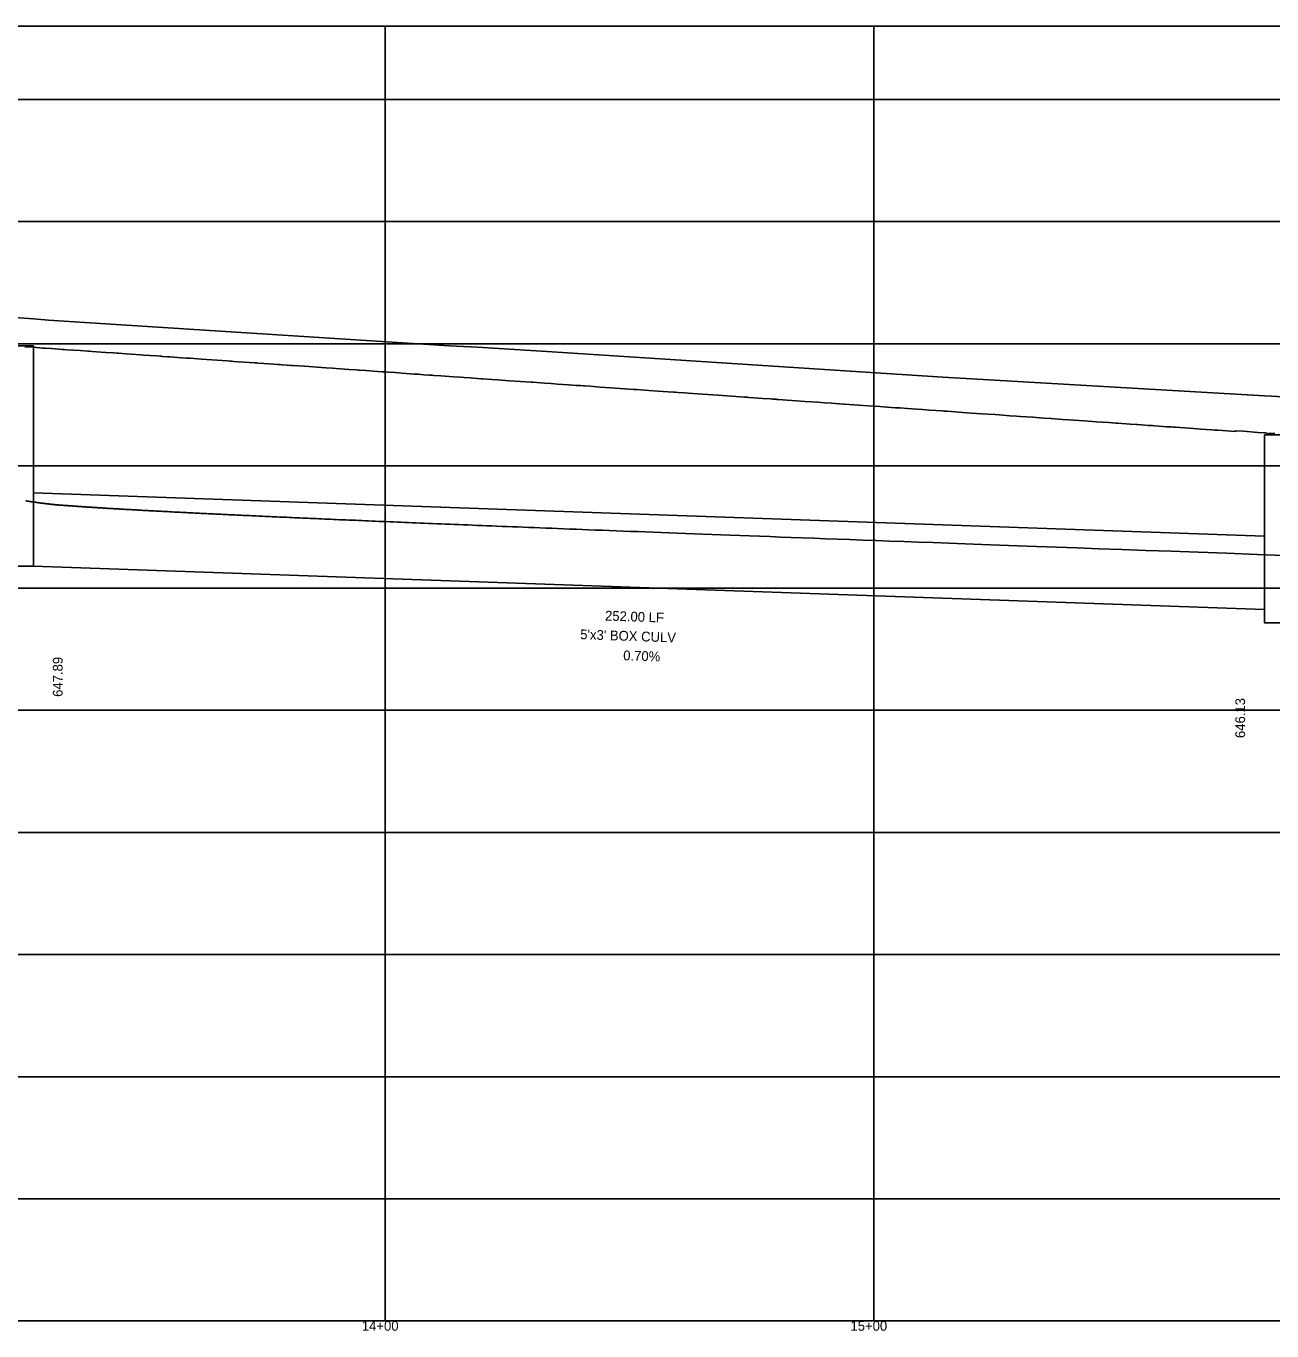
# Model space of a CAD drawing. Extents: x 2252703 to 2264864, y 13787568 to 13790989.
# Drawn here: x 2259238.5 to 2259493.5, y 13790698.5 to 13790965.5 of the extents above; entities that cross this region are included whole.
import ezdxf

# ---------------------------------------------------------------- set-up
doc = ezdxf.new("R2010")
doc.units = 0
for name, color, linetype in [('blank4', 7, 'Continuous'), ('D_DRN_PROF_HGL', 7, 'Continuous'), ('D_PROF_1', 7, 'Continuous'), ('D_PROF_NOTES_1', 7, 'Continuous'), ('Default', 7, 'Continuous'), ('Drain_PipeInside', 7, 'Continuous'), ('E_Terrain', 7, 'Continuous'), ('Inlet', 7, 'Continuous'), ('z - Construction', 7, 'Continuous')]:
    doc.layers.add(name, color=color, linetype=linetype)

msp = doc.modelspace()

# ---------------------------------------------------------------- linework, layer by layer
at = {"layer": 'blank4'}
msp.add_lwpolyline([(2257912.03, 13790700.51), (2257912.03, 13790965.51), (2261066.03, 13790965.51), (2261066.03, 13790700.51)], close=True, dxfattribs=at)
at = {"layer": 'D_DRN_PROF_HGL'}
msp.add_lwpolyline([(2259238.49, 13790868.35), (2259238.54, 13790868.34), (2259238.59, 13790868.34), (2259238.64, 13790868.33), (2259238.7, 13790868.32), (2259238.75, 13790868.31), (2259238.8, 13790868.3), (2259238.86, 13790868.29), (2259238.91, 13790868.28), (2259238.97, 13790868.27), (2259239.02, 13790868.27), (2259239.08, 13790868.26), (2259239.14, 13790868.25), (2259239.2, 13790868.24), (2259239.26, 13790868.23), (2259239.32, 13790868.22), (2259239.38, 13790868.21), (2259239.44, 13790868.2), (2259239.5, 13790868.19), (2259239.56, 13790868.18), (2259239.62, 13790868.17), (2259239.69, 13790868.16), (2259239.75, 13790868.15), (2259239.82, 13790868.14), (2259239.88, 13790868.14), (2259239.95, 13790868.13), (2259240.02, 13790868.12), (2259240.08, 13790868.11), (2259240.15, 13790868.1), (2259240.22, 13790868.09), (2259240.29, 13790868.08), (2259240.36, 13790868.07), (2259240.43, 13790868.06), (2259240.5, 13790868.05), (2259240.58, 13790868.04), (2259240.65, 13790868.03), (2259240.72, 13790868.02), (2259240.8, 13790868.01), (2259240.87, 13790868), (2259240.95, 13790867.99), (2259241.03, 13790867.98), (2259241.1, 13790867.96), (2259241.18, 13790867.95), (2259241.26, 13790867.94), (2259241.34, 13790867.93), (2259241.42, 13790867.92), (2259241.5, 13790867.91), (2259241.59, 13790867.9), (2259241.67, 13790867.89), (2259241.75, 13790867.88), (2259241.84, 13790867.87), (2259241.92, 13790867.86), (2259242.01, 13790867.85), (2259242.1, 13790867.84), (2259242.19, 13790867.82), (2259242.27, 13790867.81), (2259242.36, 13790867.8), (2259242.45, 13790867.79), (2259242.54, 13790867.78), (2259242.64, 13790867.77), (2259242.73, 13790867.76), (2259242.82, 13790867.74), (2259242.92, 13790867.73), (2259243.01, 13790867.72), (2259243.11, 13790867.71), (2259243.21, 13790867.7), (2259243.3, 13790867.69), (2259243.4, 13790867.67), (2259243.5, 13790867.66), (2259243.6, 13790867.65), (2259243.7, 13790867.64), (2259243.81, 13790867.63), (2259243.91, 13790867.61), (2259244.01, 13790867.6), (2259244.12, 13790867.59), (2259244.22, 13790867.58), (2259244.33, 13790867.58), (2259244.44, 13790867.57), (2259244.55, 13790867.56), (2259244.66, 13790867.55), (2259244.77, 13790867.54), (2259244.88, 13790867.53), (2259244.99, 13790867.52), (2259245.1, 13790867.51), (2259245.22, 13790867.5), (2259245.33, 13790867.5), (2259245.45, 13790867.49), (2259245.57, 13790867.48), (2259245.69, 13790867.47), (2259245.8, 13790867.46), (2259245.92, 13790867.45), (2259246.05, 13790867.44), (2259246.17, 13790867.43), (2259246.29, 13790867.42), (2259246.42, 13790867.41), (2259246.54, 13790867.4), (2259246.67, 13790867.39), (2259246.79, 13790867.38), (2259246.92, 13790867.37), (2259247.05, 13790867.37), (2259247.18, 13790867.36), (2259247.32, 13790867.35), (2259247.45, 13790867.34), (2259247.58, 13790867.33), (2259247.72, 13790867.32), (2259247.85, 13790867.31), (2259247.99, 13790867.3), (2259248.13, 13790867.29), (2259248.27, 13790867.28), (2259248.41, 13790867.27), (2259248.55, 13790867.26), (2259248.69, 13790867.25), (2259248.84, 13790867.24), (2259248.98, 13790867.23), (2259249.13, 13790867.22), (2259249.28, 13790867.21), (2259249.43, 13790867.2), (2259249.58, 13790867.19), (2259249.73, 13790867.18), (2259249.88, 13790867.17), (2259250.03, 13790867.16), (2259250.19, 13790867.15), (2259250.34, 13790867.13), (2259250.5, 13790867.12), (2259250.66, 13790867.11), (2259250.82, 13790867.1), (2259250.98, 13790867.09), (2259251.14, 13790867.08), (2259251.31, 13790867.07), (2259251.47, 13790867.06), (2259251.64, 13790867.05), (2259251.81, 13790867.04), (2259251.98, 13790867.03), (2259252.15, 13790867.02), (2259252.32, 13790867.01), (2259252.49, 13790866.99), (2259252.67, 13790866.98), (2259252.84, 13790866.97), (2259253.02, 13790866.96), (2259253.2, 13790866.95), (2259253.38, 13790866.94), (2259253.56, 13790866.93), (2259253.74, 13790866.92), (2259253.93, 13790866.9), (2259254.11, 13790866.89), (2259254.3, 13790866.88), (2259254.49, 13790866.87), (2259254.68, 13790866.86), (2259254.87, 13790866.85), (2259255.07, 13790866.83), (2259255.26, 13790866.82), (2259255.46, 13790866.81), (2259255.66, 13790866.8), (2259255.86, 13790866.79), (2259256.06, 13790866.77), (2259256.26, 13790866.76), (2259256.47, 13790866.75), (2259256.67, 13790866.74), (2259256.88, 13790866.73), (2259257.09, 13790866.71), (2259257.3, 13790866.7), (2259257.51, 13790866.69), (2259257.73, 13790866.68), (2259257.94, 13790866.66), (2259258.16, 13790866.65), (2259258.38, 13790866.64), (2259258.6, 13790866.63), (2259258.83, 13790866.61), (2259259.05, 13790866.6), (2259259.28, 13790866.59), (2259259.51, 13790866.57), (2259259.74, 13790866.56), (2259259.97, 13790866.55), (2259260.21, 13790866.53), (2259260.44, 13790866.52), (2259260.68, 13790866.51), (2259260.92, 13790866.49), (2259261.16, 13790866.48), (2259261.41, 13790866.47), (2259261.65, 13790866.45), (2259261.9, 13790866.44), (2259262.15, 13790866.43), (2259262.4, 13790866.41), (2259262.66, 13790866.4), (2259262.91, 13790866.39), (2259263.17, 13790866.37), (2259263.43, 13790866.36), (2259263.69, 13790866.34), (2259263.96, 13790866.33), (2259264.22, 13790866.31), (2259264.49, 13790866.3), (2259264.76, 13790866.29), (2259265.04, 13790866.27), (2259265.31, 13790866.26), (2259265.59, 13790866.24), (2259265.87, 13790866.23), (2259266.15, 13790866.21), (2259266.44, 13790866.2), (2259266.72, 13790866.18), (2259267.01, 13790866.17), (2259267.3, 13790866.15), (2259267.6, 13790866.14), (2259267.89, 13790866.12), (2259268.19, 13790866.11), (2259268.5, 13790866.09), (2259268.8, 13790866.07), (2259269.11, 13790866.06), (2259269.42, 13790866.04), (2259269.73, 13790866.03), (2259270.04, 13790866.01), (2259270.36, 13790865.99), (2259270.68, 13790865.98), (2259271, 13790865.96), (2259271.33, 13790865.95), (2259271.65, 13790865.93), (2259271.98, 13790865.91), (2259272.32, 13790865.9), (2259272.66, 13790865.88), (2259272.99, 13790865.86), (2259273.34, 13790865.85), (2259273.68, 13790865.83), (2259274.03, 13790865.81), (2259274.38, 13790865.79), (2259274.74, 13790865.78), (2259275.09, 13790865.76), (2259275.45, 13790865.74), (2259275.82, 13790865.72), (2259276.18, 13790865.71), (2259276.55, 13790865.69), (2259276.93, 13790865.67), (2259277.3, 13790865.65), (2259277.68, 13790865.63), (2259278.07, 13790865.61), (2259278.46, 13790865.6), (2259278.85, 13790865.58), (2259279.24, 13790865.56), (2259279.64, 13790865.54), (2259280.04, 13790865.52), (2259280.44, 13790865.5), (2259280.85, 13790865.48), (2259281.26, 13790865.46), (2259281.68, 13790865.44), (2259282.1, 13790865.42), (2259282.52, 13790865.4), (2259282.95, 13790865.38), (2259283.38, 13790865.36), (2259283.82, 13790865.34), (2259284.25, 13790865.32), (2259284.7, 13790865.3), (2259285.15, 13790865.28), (2259285.6, 13790865.26), (2259286.05, 13790865.24), (2259286.51, 13790865.22), (2259286.98, 13790865.2), (2259287.45, 13790865.18), (2259287.92, 13790865.15), (2259288.4, 13790865.13), (2259288.88, 13790865.11), (2259289.37, 13790865.09), (2259289.86, 13790865.07), (2259290.36, 13790865.04), (2259290.86, 13790865.02), (2259291.37, 13790865), (2259291.88, 13790864.98), (2259292.4, 13790864.95), (2259292.92, 13790864.93), (2259293.45, 13790864.91), (2259293.98, 13790864.88), (2259294.52, 13790864.86), (2259295.07, 13790864.83), (2259295.62, 13790864.81), (2259296.17, 13790864.79), (2259296.73, 13790864.76), (2259297.3, 13790864.74), (2259297.87, 13790864.71), (2259298.45, 13790864.69), (2259299.04, 13790864.66), (2259299.63, 13790864.63), (2259300.23, 13790864.61), (2259300.83, 13790864.58), (2259301.44, 13790864.56), (2259302.06, 13790864.53), (2259302.68, 13790864.5), (2259303.31, 13790864.48), (2259303.95, 13790864.45), (2259304.6, 13790864.42), (2259305.25, 13790864.39), (2259305.91, 13790864.37), (2259306.57, 13790864.34), (2259307.25, 13790864.31), (2259307.93, 13790864.28), (2259308.62, 13790864.25), (2259309.32, 13790864.22), (2259310.02, 13790864.19), (2259310.74, 13790864.16), (2259311.46, 13790864.13), (2259312.19, 13790864.1), (2259312.93, 13790864.07), (2259313.68, 13790864.04), (2259314.44, 13790864.01), (2259315.21, 13790863.97), (2259315.98, 13790863.94), (2259316.77, 13790863.91), (2259317.57, 13790863.88), (2259318.37, 13790863.84), (2259319.19, 13790863.81), (2259320.02, 13790863.78), (2259320.86, 13790863.74), (2259321.7, 13790863.71), (2259322.56, 13790863.67), (2259323.44, 13790863.64), (2259324.32, 13790863.6), (2259325.21, 13790863.56), (2259326.12, 13790863.53), (2259327.04, 13790863.49), (2259327.97, 13790863.45), (2259328.92, 13790863.41), (2259329.87, 13790863.38), (2259330.85, 13790863.34), (2259331.83, 13790863.3), (2259332.83, 13790863.26), (2259333.84, 13790863.22), (2259334.87, 13790863.18), (2259335.92, 13790863.13), (2259336.98, 13790863.09), (2259338.05, 13790863.05), (2259339.15, 13790863.01), (2259340.26, 13790862.96), (2259341.38, 13790862.92), (2259342.53, 13790862.87), (2259343.69, 13790862.83), (2259344.87, 13790862.78), (2259346.08, 13790862.73), (2259347.3, 13790862.69), (2259348.54, 13790862.64), (2259349.8, 13790862.59), (2259351.09, 13790862.54), (2259352.39, 13790862.49), (2259353.72, 13790862.44), (2259355.08, 13790862.38), (2259356.46, 13790862.33), (2259357.86, 13790862.28), (2259359.29, 13790862.22), (2259360.74, 13790862.17), (2259362.23, 13790862.11), (2259363.74, 13790862.05), (2259365.29, 13790861.99), (2259366.86, 13790861.93), (2259368.46, 13790861.87), (2259370.1, 13790861.81), (2259371.78, 13790861.74), (2259373.49, 13790861.68), (2259375.23, 13790861.61), (2259377.02, 13790861.55), (2259378.84, 13790861.48), (2259380.71, 13790861.41), (2259382.62, 13790861.34), (2259384.57, 13790861.26), (2259386.58, 13790861.19), (2259388.63, 13790861.11), (2259390.73, 13790861.03), (2259392.89, 13790860.95), (2259395.1, 13790860.87), (2259397.38, 13790860.78), (2259399.71, 13790860.7), (2259402.12, 13790860.61), (2259404.59, 13790860.52), (2259407.13, 13790860.42), (2259409.76, 13790860.33), (2259412.46, 13790860.23), (2259415.25, 13790860.12), (2259418.13, 13790860.02), (2259421.11, 13790859.91), (2259424.19, 13790859.8), (2259427.39, 13790859.68), (2259430.7, 13790859.56), (2259434.14, 13790859.43), (2259437.72, 13790859.3), (2259441.44, 13790859.17), (2259445.33, 13790859.03), (2259449.38, 13790858.88), (2259453.63, 13790858.72), (2259458.08, 13790858.56), (2259462.76, 13790858.4), (2259467.68, 13790858.22), (2259472.88, 13790858.03), (2259478.39, 13790857.83), (2259484.24, 13790857.62), (2259490.47, 13790857.4), (2259496, 13790857.2)], dxfattribs=at)
at = {"layer": 'D_PROF_1'}
msp.add_lwpolyline([(2259238.26, 13790899.89), (2259240, 13790899.77), (2259240, 13790899.77), (2259241.96, 13790899.63), (2259242.08, 13790899.62), (2259242.3, 13790899.61), (2259242.39, 13790899.6), (2259242.43, 13790899.6), (2259243.7, 13790899.51), (2259246, 13790899.35), (2259246.3, 13790899.33), (2259246.83, 13790899.29), (2259249.6, 13790899.1), (2259251.12, 13790898.99), (2259251.42, 13790898.97), (2259251.96, 13790898.93), (2259254.82, 13790898.73), (2259256.4, 13790898.62), (2259257.06, 13790898.57), (2259257.43, 13790898.55), (2259259.03, 13790898.44), (2259261.96, 13790898.23), (2259262.64, 13790898.18), (2259263.87, 13790898.1), (2259265.25, 13790898), (2259266, 13790897.95), (2259266.03, 13790897.95), (2259266.08, 13790897.94), (2259266.27, 13790897.93), (2259266.37, 13790897.92), (2259266.38, 13790897.92), (2259266.4, 13790897.92), (2259267.45, 13790897.85), (2259268.03, 13790897.81), (2259269.5, 13790897.7), (2259270.32, 13790897.65), (2259271.37, 13790897.57), (2259271.96, 13790897.53), (2259272.01, 13790897.53), (2259272.1, 13790897.52), (2259274.41, 13790897.36), (2259278.63, 13790897.06), (2259279.75, 13790896.99), (2259280.37, 13790896.94), (2259280.39, 13790896.94), (2259280.4, 13790896.94), (2259280.46, 13790896.94), (2259280.57, 13790896.93), (2259281.06, 13790896.89), (2259281.96, 13790896.83), (2259283.14, 13790896.75), (2259285.31, 13790896.6), (2259285.76, 13790896.57), (2259286, 13790896.55), (2259287.15, 13790896.47), (2259289.23, 13790896.32), (2259289.99, 13790896.27), (2259290.4, 13790896.24), (2259290.95, 13790896.2), (2259291.96, 13790896.13), (2259292.67, 13790896.08), (2259293.07, 13790896.05), (2259295.47, 13790895.89), (2259299.83, 13790895.58), (2259301.2, 13790895.48), (2259301.96, 13790895.43), (2259304.57, 13790895.25), (2259306, 13790895.15), (2259306.48, 13790895.11), (2259306.74, 13790895.1), (2259308.05, 13790895), (2259310.43, 13790894.84), (2259311.41, 13790894.77), (2259311.96, 13790894.73), (2259312.7, 13790894.68), (2259314.04, 13790894.59), (2259315.45, 13790894.49), (2259318.03, 13790894.31), (2259318.86, 13790894.25), (2259319.32, 13790894.22), (2259319.92, 13790894.17), (2259321.03, 13790894.1), (2259321.63, 13790894.05), (2259321.96, 13790894.03), (2259323.39, 13790893.93), (2259326, 13790893.75), (2259327.41, 13790893.65), (2259328.18, 13790893.6), (2259329.4, 13790893.51), (2259331.63, 13790893.35), (2259331.84, 13790893.34), (2259331.96, 13790893.33), (2259333.93, 13790893.19), (2259335.01, 13790893.12), (2259337.48, 13790892.94), (2259341.96, 13790892.63), (2259342.05, 13790892.62), (2259342.23, 13790892.61), (2259344.67, 13790892.44), (2259346, 13790892.35), (2259347.29, 13790892.26), (2259349.62, 13790892.1), (2259351.13, 13790891.99), (2259351.96, 13790891.93), (2259352.52, 13790891.89), (2259352.83, 13790891.87), (2259353.95, 13790891.79), (2259355.98, 13790891.65), (2259358.1, 13790891.5), (2259361.96, 13790891.23), (2259362.91, 13790891.16), (2259363.44, 13790891.13), (2259364.35, 13790891.06), (2259366, 13790890.95), (2259367.8, 13790890.82), (2259371.05, 13790890.59), (2259371.37, 13790890.57), (2259371.96, 13790890.53), (2259373.3, 13790890.44), (2259374.04, 13790890.39), (2259375.92, 13790890.25), (2259376.96, 13790890.18), (2259380.18, 13790889.96), (2259381.96, 13790889.83), (2259382.91, 13790889.76), (2259384.64, 13790889.64), (2259385.52, 13790889.58), (2259386, 13790889.55), (2259386.17, 13790889.54), (2259386.48, 13790889.51), (2259389.32, 13790889.32), (2259390.89, 13790889.21), (2259391.27, 13790889.18), (2259391.96, 13790889.13), (2259392.14, 13790889.12), (2259392.49, 13790889.09), (2259394.26, 13790888.97), (2259395.24, 13790888.9), (2259396.19, 13790888.83), (2259397.93, 13790888.71), (2259400.53, 13790888.53), (2259401.96, 13790888.43), (2259403.33, 13790888.33), (2259405.84, 13790888.16), (2259405.9, 13790888.16), (2259406, 13790888.15), (2259409.84, 13790887.88), (2259411.96, 13790887.73), (2259413.23, 13790887.64), (2259413.92, 13790887.59), (2259415.55, 13790887.48), (2259416.44, 13790887.42), (2259417.31, 13790887.36), (2259418.9, 13790887.25), (2259420.87, 13790887.11), (2259421.96, 13790887.03), (2259423.39, 13790886.93), (2259426, 13790886.75), (2259426.37, 13790886.72), (2259427.04, 13790886.68), (2259430.21, 13790886.45), (2259431.96, 13790886.33), (2259434.15, 13790886.18), (2259435.36, 13790886.09), (2259436.83, 13790885.99), (2259437.64, 13790885.93), (2259438.43, 13790885.88), (2259439.87, 13790885.78), (2259441.22, 13790885.68), (2259441.96, 13790885.63), (2259444.57, 13790885.45), (2259446, 13790885.35), (2259446.8, 13790885.29), (2259448.24, 13790885.19), (2259450.64, 13790885.02), (2259451.96, 13790884.93), (2259455.08, 13790884.71), (2259456.8, 13790884.59), (2259457.52, 13790884.54), (2259458.84, 13790884.45), (2259460.13, 13790884.36), (2259460.84, 13790884.31), (2259461.56, 13790884.26), (2259461.96, 13790884.23), (2259464.45, 13790884.06), (2259465.81, 13790883.96), (2259465.88, 13790883.96), (2259466, 13790883.95), (2259466.8, 13790883.89), (2259468.26, 13790883.79), (2259469.02, 13790883.74), (2259469.44, 13790883.71), (2259470.33, 13790883.64), (2259471.96, 13790883.53), (2259472.87, 13790883.47), (2259473.37, 13790883.43), (2259473.51, 13790883.42), (2259473.76, 13790883.4), (2259476.65, 13790883.2), (2259478.23, 13790883.09), (2259478.88, 13790883.05), (2259480.04, 13790882.97), (2259481.19, 13790882.89), (2259481.81, 13790882.84), (2259481.91, 13790882.83), (2259481.96, 13790882.83), (2259482.45, 13790882.8), (2259483.36, 13790882.73), (2259485.07, 13790882.61), (2259486, 13790882.55), (2259486.01, 13790882.7), (2259486.02, 13790882.69), (2259487.66, 13790882.58), (2259490.64, 13790882.37), (2259492, 13790882.28), (2259492, 13790882.28), (2259492.17, 13790882.26), (2259493, 13790882.06), (2259493.02, 13790882.2), (2259493.04, 13790882.2), (2259494.09, 13790882.13)], dxfattribs=at)
at = {"layer": 'Default'}
for p, q in [((2259312.03, 13790700.51), (2259312.03, 13790965.51)), ((2259412.03, 13790700.51), (2259412.03, 13790965.51))]:
    msp.add_line(p, q, dxfattribs=at)
at = {"layer": 'Drain_PipeInside'}
for p, q in [((2259240, 13790869.97), (2259492, 13790861.15)), ((2259240, 13790854.97), (2259492, 13790846.15))]:
    msp.add_line(p, q, dxfattribs=at)
at = {"layer": 'E_Terrain'}
msp.add_lwpolyline([(2259029.18, 13790916.51), (2259116.31, 13790912.21), (2259119.96, 13790911.95), (2259126.98, 13790911.69), (2259214.66, 13790907.14), (2259231.53, 13790906.26), (2259232, 13790906.22), (2259232, 13790906.22), (2259236, 13790905.89), (2259236, 13790905.89), (2259236.15, 13790905.87), (2259240, 13790905.58), (2259240, 13790905.58), (2259243.08, 13790905.35), (2259325.19, 13790900.09), (2259330.91, 13790899.77), (2259346.16, 13790898.83), (2259426.17, 13790893.67), (2259492, 13790889.84), (2259492, 13790889.84), (2259496, 13790889.61)], dxfattribs=at)
at = {"layer": 'Inlet'}
for points in [[(2259232, 13790900.05), (2259240, 13790900.05), (2259240, 13790854.97), (2259232, 13790854.97)], [(2259492, 13790881.85), (2259500, 13790881.85), (2259500, 13790843.36), (2259492, 13790843.36)]]:
    msp.add_lwpolyline(points, close=True, dxfattribs=at)
at = {"layer": 'z - Construction'}
for p, q in [((2257912.03, 13790950.51), (2261066.03, 13790950.51)), ((2257912.03, 13790925.51), (2261066.03, 13790925.51)), ((2257912.03, 13790900.51), (2261066.03, 13790900.51)), ((2257912.03, 13790875.51), (2261066.03, 13790875.51)), ((2257912.03, 13790850.51), (2261066.03, 13790850.51)), ((2257912.03, 13790825.51), (2261066.03, 13790825.51)), ((2257912.03, 13790800.51), (2261066.03, 13790800.51)), ((2257912.03, 13790775.51), (2261066.03, 13790775.51)), ((2257912.03, 13790750.51), (2261066.03, 13790750.51)), ((2257912.03, 13790725.51), (2261066.03, 13790725.51))]:
    msp.add_line(p, q, dxfattribs=at)

# ---------------------------------------------------------------- texts
at = {"layer": 'D_PROF_NOTES_1'}
for s, rotation, p in [('252.00 LF', 357.9955, (2259356.98, 13790843.87)), ("5'x3' BOX CULV", 357.9955, (2259351.9, 13790840.05)), ('647.89', 90, (2259246, 13790828.24)), ('0.70%', 357.9955, (2259360.7, 13790835.74)), ('646.13', 90, (2259488, 13790819.81))]:
    msp.add_text(s, height=2, rotation=rotation, dxfattribs=at).set_placement(p)
at = {"layer": 'Default'}
for s, p in [('14+00', (2259307.24, 13790698.51)), ('15+00', (2259407.24, 13790698.51))]:
    msp.add_text(s, height=2, dxfattribs=at).set_placement(p)

doc.saveas('drawing.dxf')
